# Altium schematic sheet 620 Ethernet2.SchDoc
size Letter; Organization: Toradex Solutions Inc.; Address1: 6415 Northwest Drive; Address2: Mississauga, ON, L4V 1X1; Address3: Canada
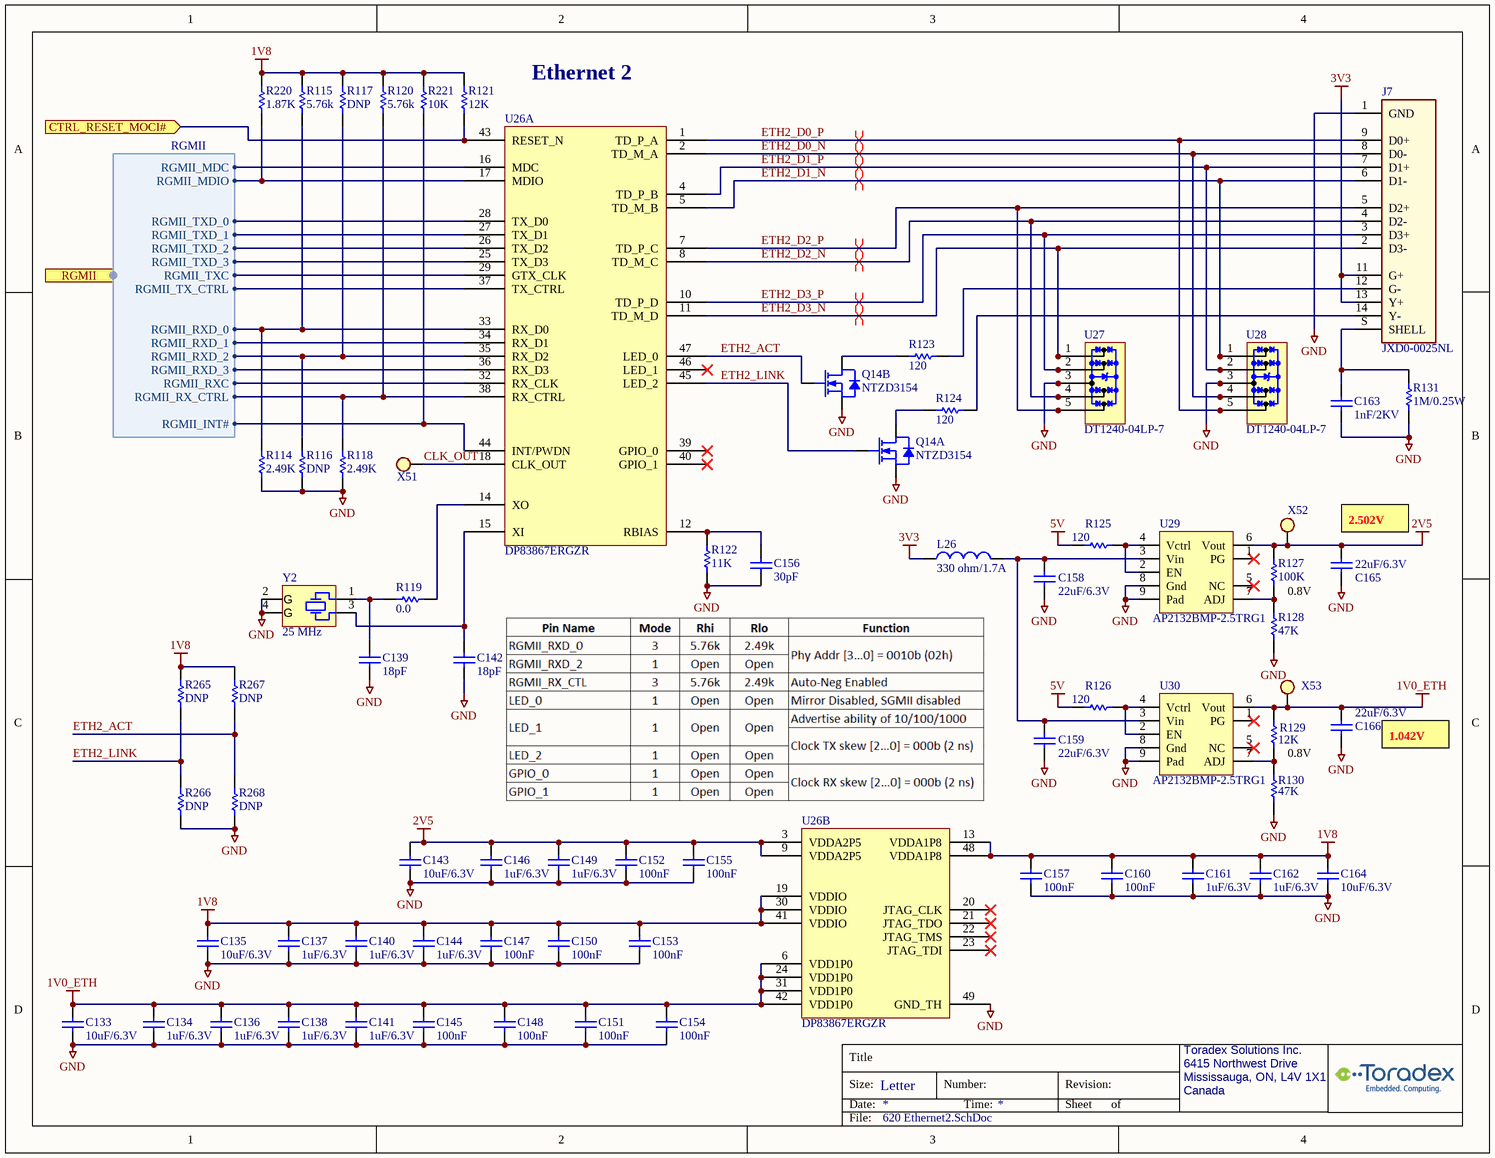
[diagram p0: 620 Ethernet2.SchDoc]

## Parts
C133  value 10uF/6.3V  [C0402_CAPC1005L]  (hidden comment: 1646-Cap-0402-10uF/6.3V)
C134  value 1uF/6.3V  [C0402_CAPC1005L]  (hidden comment: 1006-Cap-0402-1uF/6V3)
C135  value 10uF/6.3V  [C0402_CAPC1005L]  (hidden comment: 1646-Cap-0402-10uF/6.3V)
C136  value 1uF/6.3V  [C0402_CAPC1005L]  (hidden comment: 1006-Cap-0402-1uF/6V3)
C137  value 1uF/6.3V  [C0402_CAPC1005L]  (hidden comment: 1006-Cap-0402-1uF/6V3)
C138  value 1uF/6.3V  [C0402_CAPC1005L]  (hidden comment: 1006-Cap-0402-1uF/6V3)
C139  value 18pF  [C0402_CAPC1005L]  (hidden comment: 0321-Cap-0402-18pF/50V)
C140  value 1uF/6.3V  [C0402_CAPC1005L]  (hidden comment: 1006-Cap-0402-1uF/6V3)
C141  value 1uF/6.3V  [C0402_CAPC1005L]  (hidden comment: 1006-Cap-0402-1uF/6V3)
C142  value 18pF  [C0402_CAPC1005L]  (hidden comment: 0321-Cap-0402-18pF/50V)
C143  value 10uF/6.3V  [C0402_CAPC1005L]  (hidden comment: 1646-Cap-0402-10uF/6.3V)
C144  value 1uF/6.3V  [C0402_CAPC1005L]  (hidden comment: 1006-Cap-0402-1uF/6V3)
C145  100nF  [C0402_CAPC1005L]
C146  value 1uF/6.3V  [C0402_CAPC1005L]  (hidden comment: 1006-Cap-0402-1uF/6V3)
C147  100nF  [C0402_CAPC1005L]
C148  100nF  [C0402_CAPC1005L]
C149  value 1uF/6.3V  [C0402_CAPC1005L]  (hidden comment: 1006-Cap-0402-1uF/6V3)
C150  100nF  [C0402_CAPC1005L]
C151  100nF  [C0402_CAPC1005L]
C152  100nF  [C0402_CAPC1005L]
C153  100nF  [C0402_CAPC1005L]
C154  100nF  [C0402_CAPC1005L]
C155  100nF  [C0402_CAPC1005L]
C156  value 30pF  [C/0603]  (hidden comment: 0958-Cap-0603-30pF/50V)
C157  100nF  [C0402_CAPC1005L]
C158  22uF/6.3V  [C0402_CAPC1005L]
C159  22uF/6.3V  [C0402_CAPC1005L]
C160  100nF  [C0402_CAPC1005L]
C161  value 1uF/6.3V  [C0402_CAPC1005L]  (hidden comment: 1006-Cap-0402-1uF/6V3)
C162  value 1uF/6.3V  [C0402_CAPC1005L]  (hidden comment: 1006-Cap-0402-1uF/6V3)
C163  value 1nF/2KV  [C/1206]  (hidden comment: 0567-Cap-1206-1nF/2KV)
C164  value 10uF/6.3V  [C0402_CAPC1005L]  (hidden comment: 1646-Cap-0402-10uF/6.3V)
C165  22uF/6.3V  [C0402_CAPC1005L]
C166  22uF/6.3V  [C0402_CAPC1005L]
J7  JXD0-0025NL  [PULSE_JXD0-0025NL]
L26  value 330 ohm/1.7A  [INDC1608x095]  (hidden comment: 0405-Fer-0603-330ohm/1.7A)
Q14  NTZD3154  [SOT563]  (parts A,B of 2)
R114  value 2.49K  [R0402_RESC1005L]  (hidden comment: 2313-Res-0402-2.49K)
R115  value 5.76k  [R0402_RESC1005L]  (hidden comment: 2077-Res-0402-5.76K)
R116  value DNP  [R0402_RESC1005L]  (hidden comment: 0000-Res-0402-DNP)
R117  value DNP  [R0402_RESC1005L]  (hidden comment: 0000-Res-0402-DNP)
R118  value 2.49K  [R0402_RESC1005L]  (hidden comment: 2313-Res-0402-2.49K)
R119  value 0.0  [R/0603]  (hidden comment: 0195-Res-0603-0.0ohm)
R120  value 5.76k  [R0402_RESC1005L]  (hidden comment: 2077-Res-0402-5.76K)
R121  value 12K  [R0402_RESC1005L]  (hidden comment: 1537-Res-0402-12K)
R122  value 11K  [R0402_RESC1005L]  (hidden comment: 2527-Res-0402-11K)
R123  value 120  [R0402_RESC1005L]  (hidden comment: 1552-Res-0402-120)
R124  value 120  [R0402_RESC1005L]  (hidden comment: 1552-Res-0402-120)
R125  value 120  [R0402_RESC1005L]  (hidden comment: 1552-Res-0402-120)
R126  value 120  [R0402_RESC1005L]  (hidden comment: 1552-Res-0402-120)
R127  value 100K  [R0402_RESC1005L]  (hidden comment: 1977-Res-0402-100K)
R128  value 47K  [R/0603]  (hidden comment: 0042-Res-0603-47K)
R129  value 12K  [R0402_RESC1005L]  (hidden comment: 1537-Res-0402-12K)
R130  value 47K  [R/0603]  (hidden comment: 0042-Res-0603-47K)
R131  value 1M/0.25W  [R/1206]  (hidden comment: 1860-Res-1206-1M-5%-0.25W)
R220  value 1.87K  [R0402_RESC1005L]  (hidden comment: 1536-Res-0402-1.87K)
R221  value 10K  [R0402_RESC1005L]  (hidden comment: 1572-Res-0402-10K)
R265  value DNP  [R0402_RESC1005L]  (hidden comment: 0000-Res-0402-DNP)
R266  value DNP  [R0402_RESC1005L]  (hidden comment: 0000-Res-0402-DNP)
R267  value DNP  [R0402_RESC1005L]  (hidden comment: 0000-Res-0402-DNP)
R268  value DNP  [R0402_RESC1005L]  (hidden comment: 0000-Res-0402-DNP)
U26  DP83867ERGZR  [RGZ0048B]  (parts A,B of 2)
U27  DT1240-04LP-7  [10-UFDFN]
U28  DT1240-04LP-7  [10-UFDFN]
U29  AP2132BMP-2.5TRG1  [SOP-9 TP_ALT]
U30  AP2132BMP-2.5TRG1  [SOP-9 TP_ALT]
X51  000-TestPoint2  [TestPoint_3]  (value not drawn)
X52  000-TestPoint2  [TestPoint_3]  (value not drawn)
X53  000-TestPoint2  [TestPoint_3]  (value not drawn)
Y2  value 25 MHz  [XTAL_CX3225]  (hidden comment: 0987-Xtal 25MHz 3.2x2.5mm)

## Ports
CTRL_RESET_MOCI# (in), RGMII (harness RGMII)

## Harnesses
RGMII: RGMII_TXD_0, RGMII_TXD_1, RGMII_TXD_2, RGMII_TXD_3, RGMII_TXC, RGMII_TX_CTRL, RGMII_RXD_0, RGMII_RXD_1, RGMII_RXD_2, RGMII_RXD_3, RGMII_RXC, RGMII_RX_CTRL, RGMII_MDIO, RGMII_MDC, RGMII_INT#

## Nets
1V0_ETH: C133.2 C134.2 C136.2 C138.2 C141.2 C145.2 C148.2 C151.2 C154.2 C166.2 R129.2 U26.6(VDD1P0) U26.24(VDD1P0) U26.31(VDD1P0) U26.42(VDD1P0) U30.6(Vout) X53.1
1V8: C135.2 C137.2 C140.2 C144.2 C147.2 C150.2 C153.2 C157.2 C160.2 C161.2 C162.2 C164.2 R115.2 R117.1 R120.2 R121.2 R220.2 R221.2 R265.1 R267.1 U26.13(VDDA1P8) U26.19(VDDIO) U26.30(VDDIO) U26.41(VDDIO) U26.48(VDDA1P8)
2V5: C143.2 C146.2 C149.2 C152.2 C155.2 C165.2 R127.2 U26.3(VDDA2P5) U26.9(VDDA2P5) U29.6(Vout) X52.1
3V3: J7.11(G+) J7.13(Y+) L26.1
5V: R125.2 R126.2
GND: C133.1 C134.1 C135.1 C136.1 C137.1 C138.1 C139.1 C140.1 C141.1 C142.1 C143.1 C144.1 C145.1 C146.1 C147.1 C148.1 C149.1 C150.1 C151.1 C152.1 C153.1 C154.1 C155.1 C156.1 C157.1 C158.1 C159.1 C160.1 C161.1 C162.1 C163.1 C164.1 C165.1 C166.1 J7.1(GND) Q14.1(S) Q14.4(S) R114.1 R116.1 R118.1 R122.2 R128.2 R130.2 R131.2 R266.2 R268.2 U26.49(GND_TH) U27.3(GND) U27.8(GND) U28.3(GND) U28.8(GND) U29.8(Gnd) U29.9(Pad) U30.8(Gnd) U30.9(Pad) Y2.2(GND) Y2.4(GND)
CLK_OUT: U26.18(CLK_OUT) X51.1
CTRL_RESET_MOCI#: R121.1 U26.43(RESET_N) ; port CTRL_RESET_MOCI#
ETH2_ACT: Q14.5(G) R267.2 R268.1 U26.47(LED_0)
ETH2_D0_N: J7.8(D0-) U26.2(TD_M_A) U28.4(IO3) U28.7(NC)
ETH2_D0_P: J7.9(D0+) U26.1(TD_P_A) U28.5(IO4) U28.6(NC)
ETH2_D1_N: J7.6(D1-) U26.5(TD_M_B) U28.1(IO1) U28.10(NC)
ETH2_D1_P: J7.7(D1+) U26.4(TD_P_B) U28.2(IO2) U28.9(NC)
ETH2_D2_N: J7.4(D2-) U26.8(TD_M_C) U27.4(IO3) U27.7(NC)
ETH2_D2_P: J7.5(D2+) U26.7(TD_P_C) U27.5(IO4) U27.6(NC)
ETH2_D3_N: J7.2(D3-) U26.11(TD_M_D) U27.1(IO1) U27.10(NC)
ETH2_D3_P: J7.3(D3+) U26.10(TD_P_D) U27.2(IO2) U27.9(NC)
ETH2_LINK: Q14.2(G) R265.2 R266.1 U26.45(LED_2)
NetC139_2: C139.2 R119.2 Y2.1
NetC142_2: C142.2 U26.15(XI) Y2.3
NetC156_2: C156.2 R122.1 U26.12(RBIAS)
NetC158_2: C158.2 C159.2 L26.2 U29.3(Vin) U30.3(Vin)
NetC163_2: C163.2 J7.S(SHELL) R131.1
NetJ7_12: J7.12(G-) R123.2
NetJ7_14: J7.14(Y-) R124.2
NetQ14_3: Q14.3(D) R123.1
NetQ14_6: Q14.6(D) R124.1
NetR114_2: R114.2 R115.1 U26.33(RX_D0) ; port RGMII.RGMII_RXD_0
NetR116_2: R116.2 R117.2 U26.35(RX_D2) ; port RGMII.RGMII_RXD_2
NetR118_2: R118.2 R120.1 U26.38(RX_CTRL) ; port RGMII.RGMII_RX_CTRL
NetR119_1: R119.1 U26.14(XO)
NetR125_1: R125.1 U29.2(EN) U29.4(Vctrl)
NetR126_1: R126.1 U30.2(EN) U30.4(Vctrl)
NetR127_1: R127.1 R128.1 U29.7(ADJ)
NetR129_1: R129.1 R130.1 U30.7(ADJ)
NetR220_1: R220.1 U26.17(MDIO) ; port RGMII.RGMII_MDIO
NetR221_1: R221.1 U26.44(INT/PWDN) ; port RGMII.RGMII_INT#
NetU26_16: U26.16(MDC) ; port RGMII.RGMII_MDC
NetU26_25: U26.25(TX_D3) ; port RGMII.RGMII_TXD_3
NetU26_26: U26.26(TX_D2) ; port RGMII.RGMII_TXD_2
NetU26_27: U26.27(TX_D1) ; port RGMII.RGMII_TXD_1
NetU26_28: U26.28(TX_D0) ; port RGMII.RGMII_TXD_0
NetU26_29: U26.29(GTX_CLK) ; port RGMII.RGMII_TXC
NetU26_32: U26.32(RX_CLK) ; port RGMII.RGMII_RXC
NetU26_34: U26.34(RX_D1) ; port RGMII.RGMII_RXD_1
NetU26_36: U26.36(RX_D3) ; port RGMII.RGMII_RXD_3
NetU26_37: U26.37(TX_CTRL) ; port RGMII.RGMII_TX_CTRL

Not connected (* = marked no-connect by the designer): U26 20(JTAG_CLK)* 21(JTAG_TDO)* 22(JTAG_TMS)* 23(JTAG_TDI)* 39(GPIO_0)* 40(GPIO_1)* 46(LED_1)*; U29 1(PG)* 5(NC)*; U30 1(PG)* 5(NC)*

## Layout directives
differential pair; differential pair class ETH2: ETH2_D0_N, ETH2_D0_P, ETH2_D1_N, ETH2_D1_P, ETH2_D2_N, ETH2_D2_P, ETH2_D3_N, ETH2_D3_P

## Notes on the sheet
- Ethernet 2
- (near C165) 2.502V
- 0.8V
- (near C166) 1.042V

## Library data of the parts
C133 C135 C143 C164 = 1646-Cap-0402-10uF/6.3V: (-55 to 85 DegC) CAP CER 10UF 6.3V 20% X5R 0402; MfrNo: GRM155R60J106ME44D; Mfr: Murata; Alt: GRM155R60J106ME47D,C0402C106M9PACTU,04026D106MAT2A; PN: 1646
C134 C136-C138 C140 C141 C144 C146 C149 C161 C162 = 1006-Cap-0402-1uF/6V3: Cap Ceramic 1uF 6.3V X5R 20% SMD 0402 85C T/R; Mfr: Samsung; MfrNo: CL05A105MQ5NNNC; Alt: CL05A105MP5NNNC,CL05A105KQ5NNNC,CL05A105KP5NNNC,CL05A105JQ5NNNC; PN: 1006; Desc: Cap Ceramic 1uF 6.3V X5R 20% SMD 0402 85C Paper T/R
C139 C142 = 0321-Cap-0402-18pF/50V: CAP CER 18PF 50V 5% NP0 0402; MfrNo: CL05C180JB5NNNC; Mfr: Samsung Electro-Mechanics America, Inc; PN: 321; Alt: 311-1415-1-ND; Alt2: 490-5858-1-ND
C145 C147 C148 C150-C155 C157 C160 = 1566-Cap-0402-100nF/50V: (-55 to 125 DegC AEC) Cap Ceramic 0.1uF 50V X7R 10% 0402; MfrNo: GRT155R71H104KE01D; Mfr: Murata; Alt: CL05B104KB54PNC,GCM155R71H104ME02D,GCM155R71H104KE02D,GCM155R71H104KE02J; PN: 1566
C156 = 0958-Cap-0603-30pF/50V: (-55 - 125 DegC) CAP CER 30PF 50V C0G/NP0 0603; Mfr: Kyocera AVX; MfrNo: 06035A300JAT2A\4K; PN: 958; Alt: CC0603GRNPO9BN300,06031A300J4T2A
C158 C159 C165 C166 = 2404-Cap-0402-22uF/6.3V: (-55 to 85 DegC) CAP CER 22UF 6.3V 20% X5R 0402; Mfr: Murata; MfrNo: GRM155R60J226ME11D; PN: 2404
C163 = 0567-Cap-1206-1nF/2KV: CAP CER 1000PF 2KV X7R 1206; Mfr: Johanson Dielectrics Inc.; MfrNo: 202R18W102KV4E; PN: 567; Alt: 478-2956-1-ND; Alt2: 399-4819-1-ND
J7 = 1380-Conn-RJ45-GBe: (-40 to 85 DegC) CONN MAGJACK 1PORT 1000 BASE-T Isolated Taps; Mfr: Pulse; PN: 1380
L26 = 0405-Fer-0603-330ohm/1.7A: (-55 to 125 DegC) FERRITE BEAD 330 OHM 0603 1.7A 80mohm, typ 48mohm; Mfr: TDK Corporation; MfrNo: MPZ1608S331ATA00; PN: 405; TR: 445-5221-2-ND; DR: 445-5221-6-ND; DR2: 810-MPZ1608S331ATA00
Q14 = 1146-NTZD3154NT1G: (-55 to 150 DegC) MOSFET 2N-CH (dual) 20V 0.54A SOT-563 1.6x1.6mm Vth:1V Ron typ:400m@4.5V, 500m@2.5V, 700m@1.8V; Mfr: ON Semiconductor; PN: 1146; Alt: NTZD3154NT5G,PMDT290UNE,115
R114 R118 = 2313-Res-0402-2.49K: (-55 to 155 DegC) RES SMD 2.49K OHM 1% 1/16W 0402 100ppm; Mfr: Yageo; MfrNo: RC0402FR-072K49L; PN: 2313
R115 R120 = 2077-Res-0402-5.76K: (-55 to 155 DegC) RES 5.76K OHM 1/16W 1% 0402 SMD; Mfr: Stackpole Electronics; MfrNo: RMCF0402FT5K76; PN: 2077
R116 R117 R265-R268 = 0000-Res-0402-DNP: RES 0402
R119 = 0195-Res-0603-0.0ohm: RES 0.0 OHM 1/10W JUMP 0603; Mfr: Samsung; MfrNo: RC1608J000CS; Alt: 311-0.0GRCT-ND; PN: 195; Alt2: A106051CT-ND; TR: 1276-3510-2-ND
R121 = 1537-Res-0402-12K: (-55 to 155 DegC AEC) RES 12K OHM 1% 1/16W 100ppm 0402; Mfr: Stackpole Electronics; MfrNo: RMCF0402FT12K0; Alt: AC0402FR-0712KL,CRGCQ0402F12K; PN: 1537
R122 = 2527-Res-0402-11K: (-55 to 155 DegC AEC) RES SMD 11K OHM 1% 1/16W 0402 100ppm 0402; Mfr: Yageo; MfrNo: AC0402FR-0711KL; PN: 2527
R123-R126 = 1552-Res-0402-120: (-55 to 155 DegC AEC) RES 120 OHM 1% 1/16W 100ppm 0402; MfrNo: RMCF0402FT120R; Mfr: Stackpole Electronics; PN: 1552; Alt: AC0402FR-07120RL,CRGCQ0402F120R
R127 = 1977-Res-0402-100K: (-55 to 155 DegC) RES 100K OHM 1/16W 1% 0402 SMD; Mfr: Yageo; MfrNo: RC0402FR-07100KL; PN: 1977
R128 = 0042-Res-0603-47K: RES 47.0K OHM 1/10W 1% 0603 SMD; Mfr: Yageo; MfrNo: RC0603FR-0747KL; Alt: RHM47.0KCFCT-ND; Alt2: RHM47.0KHCT-ND; PN: 42; TR: 311-47.0KHRTR-ND
R129 = 1537-Res-0402-12K: (-55 to 155 DegC AEC) RES 12K OHM 1% 1/16W 100ppm 0402; Mfr: Stackpole Electronics; MfrNo: RMCF0402FT12K0; PN: 1537; Alt: AC0402FR-0712KL,CRGCQ0402F12K
R130 = 0042-Res-0603-47K: (-55 to 155 DegC) RES 47.0K OHM 1/10W 1% 0603 SMD; Mfr: Yageo; MfrNo: RC0603FR-0747KL; Alt: RHM47.0KCFCT-ND; Alt2: RHM47.0KHCT-ND; PN: 42; TR: 311-47.0KHRTR-ND
R131 = 1860-Res-1206-1M-5%-0.25W: (-55 to 155 DegC) RES SMD 1M OHM 5% 0.25W 10ppm 1206; Mfr: TE Connectivity; MfrNo: CRGCQ1206J1M0; PN: 1860; Alt: RMCF1206JT1M00, RMCF1206JG1M00, CR1206-JW-105ELF
R220 = 1536-Res-0402-1.87K: (-55 to 155 DegC AEC) RES 1.87K OHM 1% 1/16W 100ppm 0402; MfrNo: RMCF0402FT1K87; Mfr: Stackpole Electronics; Alt: AC0402FR-071K87L,RK73H1ETTP1871F,ERJ-2RKF1871X; PN: 1536
R221 = 1572-Res-0402-10K: (-55 to 155 DegC AEC) RES 10K OHM 1% 1/16W 100ppm 0402; Mfr: Stackpole Electronics; MfrNo: RMCF0402FT10K0; Alt: AC0402FR-0710KL,AC0402FR-1310KL,CRGCQ0402F10K; PN: 1572
U26 = 2076-DP83867ERGZR: (-40 to 105 DegC) Eth Phy RGMII 1GBASE-T VQFN-48; Mfr: Texas Instruments; PN: 2076
U27 U28 = 1657-DT1240-04LP-7: (-55 to 85 DegC) IC TVS DIODE 4ch Vrm:5.5V Vcl:11V@5.5A 10-UFDFN 0.5mm; Mfr: Diodes; PN: 1657
U29 U30 = 1467-AP2132BMP-2.5: (-40 to 85 DegC) IC REG LDO LINEAR POS ADJ 5V 2A 8SO; Mfr: Diodes; PN: 1467; Desc: (-40 to 85 DegC) IC REG BUCK ADJ Sync 5A Vin:3.8 to 40V 100-2200kHz FSS (spread spectrum) MaxDuty:100% SO-8EP; Note: These can be also used with adjust Voltage circuit: AP2132BMP-1.2TRG1, AP2132BMP-1.5TRG1
X51-X53 = 000-TestPoint2: TestPoint SMD; Note: PCB footprint only, no parts to buy or assemble
Y2 = 0987-Xtal 25MHz 3.2x2.5mm: (-40 to 85 DegC) CRYSTAL 25.0MHZ 18PF SMD +-50ppm +-20ppm 3.2x2.5mm; MfrNo: LFXTAL055299REEL; Mfr: IQD Frequency Products; PN: 987; Note: caps: 18pF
